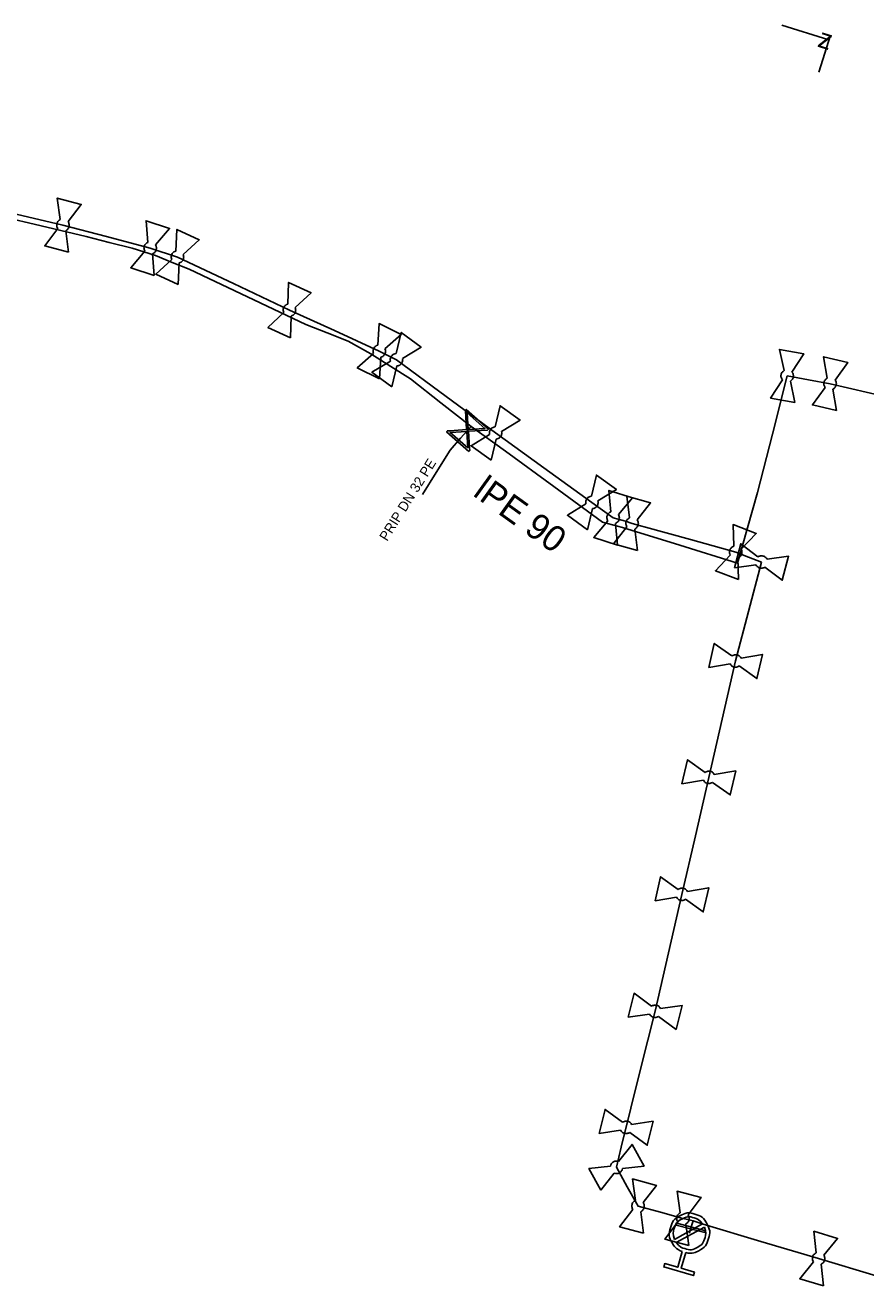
# Model space of a CAD drawing. Extents: x -638315 to -636370, y -1116147 to -1115110.
# Drawn here: x -637211.2 to -637168.7, y -1116102.1 to -1116038.4 of the extents above; entities that cross this region are included whole.
import ezdxf

# ---------------------------------------------------------------- set-up
doc = ezdxf.new("R2010")
doc.units = 0
for name, color, linetype in [('Default', 7, 'Continuous'), ('VP Hydrant', 7, 'Continuous'), ('VP Kótování', 7, 'Continuous'), ('VP Lomový bod', 7, 'Continuous'), ('VP Popis přípojky', 7, 'Continuous'), ('VP Přípojka', 7, 'Continuous'), ('VP Řad', 7, 'Continuous'), ('VP Řad - popis', 7, 'Continuous'), ('VP Šoupě', 7, 'Continuous')]:
    doc.layers.add(name, color=color, linetype=linetype)

msp = doc.modelspace()

# ---------------------------------------------------------------- linework, layer by layer
at = {"layer": 'Default'}
for points in [[(-637209.589, -1116048.648), (-637209.618, -1116048.605), (-637209.632, -1116048.553), (-637209.653, -1116048.47), (-637209.632, -1116048.391), (-637209.611, -1116048.311), (-637209.553, -1116048.251), (-637209.515, -1116048.212), (-637209.467, -1116048.189)], [(-637209.073, -1116048.293), (-637209.042, -1116048.336), (-637209.028, -1116048.389), (-637209.007, -1116048.47), (-637209.028, -1116048.549), (-637209.049, -1116048.629), (-637209.109, -1116048.691), (-637209.146, -1116048.729), (-637209.193, -1116048.752)], [(-637205.189, -1116049.793), (-637205.215, -1116049.748), (-637205.226, -1116049.696), (-637205.242, -1116049.611), (-637205.217, -1116049.533), (-637205.192, -1116049.455), (-637205.13, -1116049.399), (-637205.089, -1116049.362), (-637205.04, -1116049.342)], [(-637204.653, -1116049.468), (-637204.625, -1116049.513), (-637204.614, -1116049.567), (-637204.598, -1116049.649), (-637204.623, -1116049.727), (-637204.648, -1116049.805), (-637204.712, -1116049.863), (-637204.751, -1116049.9), (-637204.8, -1116049.92)], [(-637203.827, -1116050.207), (-637203.848, -1116050.16), (-637203.852, -1116050.106), (-637203.857, -1116050.02), (-637203.822, -1116049.946), (-637203.787, -1116049.872), (-637203.719, -1116049.824), (-637203.674, -1116049.792), (-637203.623, -1116049.779)], [(-637203.254, -1116049.953), (-637203.233, -1116050.001), (-637203.229, -1116050.056), (-637203.223, -1116050.14), (-637203.258, -1116050.214), (-637203.293, -1116050.288), (-637203.364, -1116050.338), (-637203.407, -1116050.369), (-637203.458, -1116050.382)], [(-637198.166, -1116052.891), (-637198.187, -1116052.844), (-637198.192, -1116052.79), (-637198.198, -1116052.704), (-637198.164, -1116052.63), (-637198.13, -1116052.555), (-637198.062, -1116052.506), (-637198.018, -1116052.474), (-637197.967, -1116052.46)], [(-637197.596, -1116052.63), (-637197.574, -1116052.677), (-637197.569, -1116052.732), (-637197.562, -1116052.816), (-637197.596, -1116052.89), (-637197.63, -1116052.965), (-637197.7, -1116053.016), (-637197.743, -1116053.047), (-637197.794, -1116053.061)], [(-637193.629, -1116054.963), (-637193.649, -1116054.915), (-637193.653, -1116054.861), (-637193.656, -1116054.775), (-637193.62, -1116054.702), (-637193.584, -1116054.628), (-637193.514, -1116054.581), (-637193.469, -1116054.55), (-637193.418, -1116054.537)], [(-637193.052, -1116054.718), (-637193.031, -1116054.767), (-637193.028, -1116054.821), (-637193.024, -1116054.905), (-637193.06, -1116054.978), (-637193.096, -1116055.052), (-637193.168, -1116055.101), (-637193.211, -1116055.131), (-637193.263, -1116055.144)], [(-637192.776, -1116055.34), (-637192.787, -1116055.289), (-637192.782, -1116055.236), (-637192.77, -1116055.15), (-637192.721, -1116055.084), (-637192.673, -1116055.019), (-637192.596, -1116054.984), (-637192.546, -1116054.962), (-637192.493, -1116054.958)], [(-637192.165, -1116055.201), (-637192.153, -1116055.252), (-637192.16, -1116055.306), (-637192.17, -1116055.39), (-637192.219, -1116055.456), (-637192.267, -1116055.521), (-637192.347, -1116055.557), (-637192.395, -1116055.579), (-637192.447, -1116055.583)], [(-637172.964, -1116056.288), (-637172.996, -1116056.247), (-637173.015, -1116056.197), (-637173.042, -1116056.115), (-637173.028, -1116056.035), (-637173.013, -1116055.954), (-637172.959, -1116055.889), (-637172.924, -1116055.847), (-637172.879, -1116055.821)], [(-637172.477, -1116055.893), (-637172.444, -1116055.934), (-637172.426, -1116055.985), (-637172.398, -1116056.065), (-637172.412, -1116056.145), (-637172.427, -1116056.226), (-637172.482, -1116056.293), (-637172.516, -1116056.334), (-637172.561, -1116056.36)], [(-637170.803, -1116056.666), (-637170.834, -1116056.624), (-637170.85, -1116056.572), (-637170.873, -1116056.489), (-637170.854, -1116056.41), (-637170.836, -1116056.33), (-637170.779, -1116056.268), (-637170.742, -1116056.228), (-637170.695, -1116056.203)], [(-637170.298, -1116056.295), (-637170.266, -1116056.338), (-637170.251, -1116056.39), (-637170.227, -1116056.471), (-637170.246, -1116056.55), (-637170.264, -1116056.63), (-637170.323, -1116056.694), (-637170.358, -1116056.734), (-637170.405, -1116056.758)], [(-637187.766, -1116059.043), (-637187.777, -1116058.993), (-637187.772, -1116058.939), (-637187.761, -1116058.854), (-637187.714, -1116058.787), (-637187.666, -1116058.721), (-637187.589, -1116058.686), (-637187.54, -1116058.663), (-637187.487, -1116058.659)], [(-637187.156, -1116058.897), (-637187.143, -1116058.948), (-637187.15, -1116059.003), (-637187.159, -1116059.086), (-637187.206, -1116059.153), (-637187.254, -1116059.219), (-637187.333, -1116059.255), (-637187.381, -1116059.278), (-637187.434, -1116059.282)], [(-637182.895, -1116062.553), (-637182.907, -1116062.503), (-637182.902, -1116062.45), (-637182.891, -1116062.364), (-637182.844, -1116062.297), (-637182.796, -1116062.231), (-637182.719, -1116062.196), (-637182.67, -1116062.173), (-637182.617, -1116062.169)], [(-637182.286, -1116062.407), (-637182.273, -1116062.458), (-637182.279, -1116062.512), (-637182.289, -1116062.596), (-637182.336, -1116062.663), (-637182.384, -1116062.729), (-637182.463, -1116062.765), (-637182.511, -1116062.788), (-637182.564, -1116062.792)], [(-637181.788, -1116063.414), (-637181.815, -1116063.37), (-637181.826, -1116063.317), (-637181.843, -1116063.233), (-637181.818, -1116063.155), (-637181.793, -1116063.077), (-637181.731, -1116063.02), (-637181.691, -1116062.983), (-637181.642, -1116062.962)], [(-637181.254, -1116063.087), (-637181.226, -1116063.131), (-637181.215, -1116063.185), (-637181.197, -1116063.267), (-637181.222, -1116063.345), (-637181.247, -1116063.423), (-637181.311, -1116063.482), (-637181.35, -1116063.519), (-637181.398, -1116063.539)], [(-637180.822, -1116063.714), (-637180.85, -1116063.671), (-637180.863, -1116063.619), (-637180.883, -1116063.535), (-637180.861, -1116063.456), (-637180.839, -1116063.377), (-637180.779, -1116063.318), (-637180.741, -1116063.279), (-637180.693, -1116063.257)], [(-637180.3, -1116063.367), (-637180.27, -1116063.41), (-637180.257, -1116063.464), (-637180.237, -1116063.545), (-637180.259, -1116063.624), (-637180.281, -1116063.703), (-637180.342, -1116063.764), (-637180.38, -1116063.802), (-637180.428, -1116063.824)], [(-637175.597, -1116065.139), (-637175.621, -1116065.093), (-637175.629, -1116065.04), (-637175.641, -1116064.954), (-637175.612, -1116064.878), (-637175.582, -1116064.801), (-637175.517, -1116064.748), (-637175.475, -1116064.713), (-637175.425, -1116064.696)], [(-637175.045, -1116064.842), (-637175.019, -1116064.889), (-637175.011, -1116064.943), (-637174.999, -1116065.026), (-637175.028, -1116065.102), (-637175.058, -1116065.179), (-637175.125, -1116065.234), (-637175.165, -1116065.268), (-637175.215, -1116065.285)], [(-637173.843, -1116065.747), (-637173.886, -1116065.778), (-637173.939, -1116065.791), (-637174.02, -1116065.813), (-637174.099, -1116065.792), (-637174.178, -1116065.772), (-637174.241, -1116065.711), (-637174.279, -1116065.675), (-637174.302, -1116065.627)], [(-637174.198, -1116065.231), (-637174.155, -1116065.202), (-637174.104, -1116065.188), (-637174.02, -1116065.167), (-637173.941, -1116065.188), (-637173.862, -1116065.208), (-637173.801, -1116065.267), (-637173.762, -1116065.305), (-637173.739, -1116065.353)], [(-637175.516, -1116070.237), (-637175.474, -1116070.206), (-637175.423, -1116070.191), (-637175.34, -1116070.167), (-637175.26, -1116070.185), (-637175.18, -1116070.204), (-637175.118, -1116070.261), (-637175.078, -1116070.297), (-637175.054, -1116070.344)], [(-637175.145, -1116070.742), (-637175.187, -1116070.773), (-637175.24, -1116070.789), (-637175.32, -1116070.813), (-637175.4, -1116070.795), (-637175.48, -1116070.776), (-637175.544, -1116070.718), (-637175.583, -1116070.682), (-637175.608, -1116070.635)], [(-637176.495, -1116076.622), (-637176.537, -1116076.653), (-637176.59, -1116076.669), (-637176.67, -1116076.693), (-637176.75, -1116076.675), (-637176.83, -1116076.656), (-637176.894, -1116076.598), (-637176.933, -1116076.562), (-637176.958, -1116076.515)], [(-637176.866, -1116076.117), (-637176.824, -1116076.086), (-637176.773, -1116076.071), (-637176.69, -1116076.047), (-637176.61, -1116076.065), (-637176.53, -1116076.084), (-637176.468, -1116076.141), (-637176.428, -1116076.178), (-637176.403, -1116076.224)], [(-637178.226, -1116082.027), (-637178.184, -1116081.996), (-637178.133, -1116081.981), (-637178.05, -1116081.957), (-637177.97, -1116081.975), (-637177.89, -1116081.994), (-637177.828, -1116082.051), (-637177.788, -1116082.088), (-637177.763, -1116082.134)], [(-637177.855, -1116082.532), (-637177.897, -1116082.563), (-637177.95, -1116082.579), (-637178.03, -1116082.603), (-637178.11, -1116082.585), (-637178.19, -1116082.566), (-637178.254, -1116082.508), (-637178.293, -1116082.472), (-637178.318, -1116082.425)], [(-637179.581, -1116087.933), (-637179.538, -1116087.904), (-637179.487, -1116087.889), (-637179.403, -1116087.867), (-637179.324, -1116087.887), (-637179.245, -1116087.907), (-637179.184, -1116087.965), (-637179.144, -1116088.003), (-637179.121, -1116088.05)], [(-637179.22, -1116088.445), (-637179.263, -1116088.476), (-637179.316, -1116088.491), (-637179.397, -1116088.513), (-637179.476, -1116088.493), (-637179.555, -1116088.473), (-637179.618, -1116088.413), (-637179.657, -1116088.377), (-637179.68, -1116088.33)], [(-637181.042, -1116093.796), (-637181, -1116093.766), (-637180.948, -1116093.751), (-637180.865, -1116093.729), (-637180.786, -1116093.749), (-637180.706, -1116093.769), (-637180.645, -1116093.826), (-637180.605, -1116093.864), (-637180.582, -1116093.911)], [(-637180.68, -1116094.307), (-637180.723, -1116094.338), (-637180.775, -1116094.353), (-637180.856, -1116094.375), (-637180.936, -1116094.356), (-637181.015, -1116094.336), (-637181.078, -1116094.276), (-637181.117, -1116094.24), (-637181.141, -1116094.193)], [(-637181.658, -1116096.006), (-637181.647, -1116095.956), (-637181.619, -1116095.91), (-637181.573, -1116095.837), (-637181.502, -1116095.797), (-637181.43, -1116095.757), (-637181.346, -1116095.758), (-637181.292, -1116095.758), (-637181.242, -1116095.777)], [(-637181.044, -1116096.133), (-637181.054, -1116096.185), (-637181.083, -1116096.231), (-637181.127, -1116096.303), (-637181.198, -1116096.343), (-637181.27, -1116096.383), (-637181.357, -1116096.382), (-637181.41, -1116096.382), (-637181.459, -1116096.364)], [(-637180.521, -1116098.206), (-637180.549, -1116098.162), (-637180.563, -1116098.111), (-637180.583, -1116098.027), (-637180.561, -1116097.948), (-637180.54, -1116097.869), (-637180.481, -1116097.809), (-637180.442, -1116097.77), (-637180.394, -1116097.748)], [(-637180.001, -1116097.855), (-637179.971, -1116097.899), (-637179.958, -1116097.952), (-637179.937, -1116098.033), (-637179.959, -1116098.112), (-637179.98, -1116098.191), (-637180.041, -1116098.253), (-637180.078, -1116098.291), (-637180.126, -1116098.313)], [(-637178.023, -1116100.332), (-637178.36, -1116100.205), (-637178.536, -1116099.884), (-637178.735, -1116099.522), (-637178.621, -1116099.122), (-637178.507, -1116098.724), (-637178.144, -1116098.525), (-637177.782, -1116098.325), (-637177.382, -1116098.439), (-637176.986, -1116098.553), (-637176.785, -1116098.914), (-637176.584, -1116099.276), (-637176.698, -1116099.674), (-637176.813, -1116100.074), (-637177.173, -1116100.275), (-637177.493, -1116100.456), (-637177.846, -1116100.383)], [(-637176.996, -1116098.928), (-637177.157, -1116098.701), (-637177.435, -1116098.621), (-637177.758, -1116098.529), (-637178.052, -1116098.691), (-637178.347, -1116098.854), (-637178.44, -1116099.178), (-637178.519, -1116099.456), (-637178.412, -1116099.713)], [(-637178.248, -1116098.83), (-637178.277, -1116098.787), (-637178.291, -1116098.736), (-637178.313, -1116098.652), (-637178.293, -1116098.573), (-637178.273, -1116098.494), (-637178.214, -1116098.433), (-637178.177, -1116098.393), (-637178.129, -1116098.37)], [(-637177.734, -1116098.471), (-637177.703, -1116098.514), (-637177.689, -1116098.567), (-637177.667, -1116098.648), (-637177.687, -1116098.727), (-637177.707, -1116098.806), (-637177.767, -1116098.869), (-637177.804, -1116098.908), (-637177.851, -1116098.931)], [(-637178.324, -1116099.872), (-637178.164, -1116100.103), (-637177.883, -1116100.183), (-637177.558, -1116100.277), (-637177.264, -1116100.114), (-637176.971, -1116099.951), (-637176.878, -1116099.626), (-637176.797, -1116099.345), (-637176.908, -1116099.087)], [(-637171.395, -1116100.849), (-637171.422, -1116100.805), (-637171.435, -1116100.753), (-637171.453, -1116100.669), (-637171.429, -1116100.59), (-637171.406, -1116100.512), (-637171.345, -1116100.454), (-637171.306, -1116100.416), (-637171.257, -1116100.395)], [(-637170.867, -1116100.511), (-637170.838, -1116100.556), (-637170.826, -1116100.609), (-637170.807, -1116100.691), (-637170.831, -1116100.77), (-637170.854, -1116100.848), (-637170.917, -1116100.908), (-637170.954, -1116100.945), (-637171.003, -1116100.966)]]:
    msp.add_open_spline(points, degree=3, dxfattribs=at)
at = {"layer": 'VP Hydrant'}
for points in [[(-637178.412, -1116099.713), (-637176.996, -1116098.928)], [(-637176.908, -1116099.087), (-637178.324, -1116099.872)], [(-637177.846, -1116100.383), (-637178.072, -1116101.171), (-637177.41, -1116101.361), (-637177.46, -1116101.538), (-637178.962, -1116101.107), (-637178.912, -1116100.931), (-637178.249, -1116101.121), (-637178.023, -1116100.332)]]:
    msp.add_lwpolyline(points, dxfattribs=at)
at = {"layer": 'VP Kótování'}
for points in [[(-637172.998, -1116038.369), (-637170.611, -1116039.112)], [(-637171.117, -1116040.739), (-637170.536, -1116038.874)]]:
    msp.add_lwpolyline(points, dxfattribs=at)
at = {"layer": 'VP Lomový bod'}
for points in [[(-637209.467, -1116048.189), (-637209.616, -1116047.102), (-637208.408, -1116047.42), (-637209.073, -1116048.293)], [(-637205.04, -1116049.342), (-637205.127, -1116048.248), (-637203.938, -1116048.635), (-637204.653, -1116049.468)], [(-637209.044, -1116049.838), (-637210.252, -1116049.52), (-637209.589, -1116048.648)], [(-637209.193, -1116048.752), (-637209.044, -1116049.838)], [(-637203.623, -1116049.779), (-637203.57, -1116048.683), (-637202.44, -1116049.218), (-637203.254, -1116049.953)], [(-637204.713, -1116051.012), (-637205.902, -1116050.625), (-637205.189, -1116049.793)], [(-637204.8, -1116049.92), (-637204.713, -1116051.012)], [(-637203.51, -1116051.477), (-637204.64, -1116050.942), (-637203.827, -1116050.207)], [(-637203.458, -1116050.382), (-637203.51, -1116051.477)], [(-637197.967, -1116052.46), (-637197.928, -1116051.363), (-637196.791, -1116051.884), (-637197.596, -1116052.63)], [(-637197.832, -1116054.157), (-637198.969, -1116053.636), (-637198.166, -1116052.891)], [(-637197.794, -1116053.061), (-637197.832, -1116054.157)], [(-637193.418, -1116054.537), (-637193.346, -1116053.442), (-637192.226, -1116053.996), (-637193.052, -1116054.718)], [(-637192.493, -1116054.958), (-637192.23, -1116053.893), (-637191.225, -1116054.636), (-637192.165, -1116055.201)], [(-637172.879, -1116055.821), (-637173.114, -1116054.749), (-637171.884, -1116054.97), (-637172.477, -1116055.893)], [(-637193.334, -1116056.238), (-637194.454, -1116055.684), (-637193.629, -1116054.963)], [(-637192.71, -1116056.647), (-637193.715, -1116055.904), (-637192.776, -1116055.34)], [(-637193.263, -1116055.144), (-637193.334, -1116056.238)], [(-637192.447, -1116055.583), (-637192.71, -1116056.647)], [(-637170.695, -1116056.203), (-637170.877, -1116055.121), (-637169.659, -1116055.403), (-637170.298, -1116056.295)], [(-637172.326, -1116057.431), (-637173.556, -1116057.21), (-637172.964, -1116056.288)], [(-637172.561, -1116056.36), (-637172.326, -1116057.431)], [(-637170.223, -1116057.839), (-637171.441, -1116057.557), (-637170.803, -1116056.666)], [(-637170.405, -1116056.758), (-637170.223, -1116057.839)], [(-637187.487, -1116058.659), (-637187.236, -1116057.591), (-637186.222, -1116058.321), (-637187.156, -1116058.897)], [(-637187.684, -1116060.349), (-637188.698, -1116059.619), (-637187.766, -1116059.043)], [(-637187.434, -1116059.282), (-637187.684, -1116060.349)], [(-637182.617, -1116062.169), (-637182.367, -1116061.1), (-637181.353, -1116061.83), (-637182.286, -1116062.407)], [(-637181.642, -1116062.962), (-637181.734, -1116061.869), (-637180.544, -1116062.25), (-637181.254, -1116063.087)], [(-637182.813, -1116063.86), (-637183.827, -1116063.13), (-637182.895, -1116062.553)], [(-637180.693, -1116063.257), (-637180.826, -1116062.168), (-637179.622, -1116062.504), (-637180.3, -1116063.367)], [(-637182.564, -1116062.792), (-637182.813, -1116063.86)], [(-637181.306, -1116064.631), (-637182.496, -1116064.25), (-637181.788, -1116063.414)], [(-637180.294, -1116064.912), (-637181.498, -1116064.576), (-637180.822, -1116063.714)], [(-637181.398, -1116063.539), (-637181.306, -1116064.631)], [(-637180.428, -1116063.824), (-637180.294, -1116064.912)], [(-637175.425, -1116064.696), (-637175.455, -1116063.599), (-637174.288, -1116064.048), (-637175.045, -1116064.842)], [(-637175.185, -1116066.381), (-637176.352, -1116065.932), (-637175.597, -1116065.139)], [(-637175.388, -1116065.778), (-637175.071, -1116064.569), (-637174.198, -1116065.231)], [(-637174.302, -1116065.627), (-637175.388, -1116065.778)], [(-637175.215, -1116065.285), (-637175.185, -1116066.381)], [(-637173.739, -1116065.353), (-637172.652, -1116065.202), (-637172.969, -1116066.411), (-637173.843, -1116065.747)], [(-637176.688, -1116070.819), (-637176.408, -1116069.601), (-637175.516, -1116070.237)], [(-637175.054, -1116070.344), (-637173.972, -1116070.161), (-637174.252, -1116071.379), (-637175.145, -1116070.742)], [(-637175.608, -1116070.635), (-637176.688, -1116070.819)], [(-637178.038, -1116076.699), (-637177.758, -1116075.481), (-637176.866, -1116076.117)], [(-637176.958, -1116076.515), (-637178.038, -1116076.699)], [(-637176.403, -1116076.224), (-637175.322, -1116076.041), (-637175.602, -1116077.259), (-637176.495, -1116076.622)], [(-637179.398, -1116082.609), (-637179.118, -1116081.391), (-637178.226, -1116082.027)], [(-637177.763, -1116082.134), (-637176.682, -1116081.951), (-637176.962, -1116083.169), (-637177.855, -1116082.532)], [(-637178.318, -1116082.425), (-637179.398, -1116082.609)], [(-637180.765, -1116088.492), (-637180.46, -1116087.28), (-637179.581, -1116087.933)], [(-637179.121, -1116088.05), (-637178.035, -1116087.888), (-637178.34, -1116089.1), (-637179.22, -1116088.445)], [(-637179.68, -1116088.33), (-637180.765, -1116088.492)], [(-637182.224, -1116094.359), (-637181.924, -1116093.145), (-637181.042, -1116093.796)], [(-637180.582, -1116093.911), (-637179.497, -1116093.746), (-637179.797, -1116094.959), (-637180.68, -1116094.307)], [(-637181.141, -1116094.193), (-637182.224, -1116094.359)], [(-637181.242, -1116095.777), (-637180.561, -1116094.916), (-637179.954, -1116096.009), (-637181.044, -1116096.133)], [(-637182.139, -1116097.224), (-637182.746, -1116096.131), (-637181.658, -1116096.006)], [(-637181.459, -1116096.364), (-637182.139, -1116097.224)], [(-637180.394, -1116097.748), (-637180.534, -1116096.659), (-637179.328, -1116096.989), (-637180.001, -1116097.855)], [(-637178.129, -1116098.37), (-637178.287, -1116097.284), (-637177.076, -1116097.593), (-637177.734, -1116098.471)], [(-637179.986, -1116099.401), (-637181.192, -1116099.071), (-637180.521, -1116098.206)], [(-637180.126, -1116098.313), (-637179.986, -1116099.401)], [(-637177.693, -1116100.016), (-637178.904, -1116099.707), (-637178.248, -1116098.83)], [(-637177.851, -1116098.931), (-637177.693, -1116100.016)], [(-637171.257, -1116100.395), (-637171.371, -1116099.303), (-637170.173, -1116099.661), (-637170.867, -1116100.511)], [(-637170.889, -1116102.057), (-637172.087, -1116101.699), (-637171.395, -1116100.849)], [(-637171.003, -1116100.966), (-637170.889, -1116102.057)]]:
    msp.add_lwpolyline(points, dxfattribs=at)
at = {"layer": 'VP Přípojka'}
for points in [[(-637188.7, -1116058.64), (-637188.879, -1116058.842), (-637189.23, -1116059.24), (-637189.76, -1116059.84), (-637190.46, -1116060.96), (-637191.16, -1116062.08)], [(-637177.66, -1116099.4), (-637177.59, -1116099.13), (-637177.48, -1116098.78)]]:
    msp.add_lwpolyline(points, dxfattribs=at)
at = {"layer": 'VP Řad'}
for points in [[(-637167.635, -1116057.155), (-637170.55, -1116056.48), (-637171.635, -1116056.285), (-637172.72, -1116056.09), (-637173.47, -1116059.035), (-637174.22, -1116061.98), (-637174.73, -1116063.76), (-637175.24, -1116065.54), (-637178.14, -1116064.64), (-637181.04, -1116063.74), (-637181.55, -1116063.605), (-637182.06, -1116063.47), (-637184.51, -1116061.68), (-637186.96, -1116059.89), (-637188.7, -1116058.64), (-637190.23, -1116057.44), (-637191.76, -1116056.24), (-637192.76, -1116055.605), (-637193.76, -1116054.97), (-637194.335, -1116054.65), (-637194.91, -1116054.33), (-637195.98, -1116053.91), (-637197.05, -1116053.49), (-637200, -1116052.09), (-637202.95, -1116050.69), (-637203.805, -1116050.35), (-637204.66, -1116050.01), (-637205.245, -1116049.825), (-637205.83, -1116049.64), (-637206.995, -1116049.34), (-637208.16, -1116049.04), (-637211.07, -1116048.36), (-637213.98, -1116047.68)], [(-637168.22, -1116101.55), (-637171.13, -1116100.68), (-637174.05, -1116099.815), (-637176.97, -1116098.95), (-637177.225, -1116098.865), (-637177.48, -1116098.78), (-637177.735, -1116098.715), (-637177.99, -1116098.65), (-637179.125, -1116098.34), (-637180.26, -1116098.03), (-637180.805, -1116097.05), (-637181.35, -1116096.07), (-637181.11, -1116095.06), (-637180.135, -1116091.12), (-637179.4, -1116088.19), (-637178.72, -1116085.235), (-637178.04, -1116082.28), (-637177.36, -1116079.325), (-637176.68, -1116076.37), (-637176.005, -1116073.43), (-637175.33, -1116070.49), (-637174.675, -1116067.99), (-637174.02, -1116065.49), (-637174.67, -1116065.24), (-637175.32, -1116064.99), (-637177.6, -1116064.36), (-637179.88, -1116063.73), (-637180.13, -1116063.66), (-637180.56, -1116063.54), (-637180.9, -1116063.42), (-637181.27, -1116063.33), (-637181.52, -1116063.25), (-637182.055, -1116062.865), (-637182.59, -1116062.48), (-637185.025, -1116060.725), (-637187.46, -1116058.97), (-637189.965, -1116057.12), (-637192.47, -1116055.27), (-637193.34, -1116054.84), (-637195.61, -1116053.8), (-637197.88, -1116052.76), (-637200.71, -1116051.42), (-637203.54, -1116050.08), (-637204.92, -1116049.63), (-637207.125, -1116049.05), (-637209.33, -1116048.47), (-637212.265, -1116047.785)]]:
    msp.add_lwpolyline(points, dxfattribs=at)
at = {"layer": 'VP Šoupě'}
for points in [[(-637188.814, -1116059.902), (-637189.938, -1116058.909), (-637189.895, -1116058.86), (-637189.766, -1116058.856), (-637188.928, -1116058.803), (-637188.989, -1116057.834), (-637188.945, -1116057.785), (-637187.821, -1116058.778), (-637187.865, -1116058.827), (-637188.835, -1116058.885), (-637188.782, -1116059.724), (-637188.77, -1116059.853), (-637188.814, -1116059.902)], [(-637188.813, -1116059.901), (-637189.937, -1116058.908), (-637189.894, -1116058.858), (-637189.765, -1116058.855), (-637188.927, -1116058.802), (-637188.988, -1116057.833), (-637188.944, -1116057.784), (-637187.82, -1116058.777), (-637187.864, -1116058.826), (-637188.833, -1116058.884), (-637188.78, -1116059.722), (-637188.769, -1116059.851), (-637188.813, -1116059.901)], [(-637188.893, -1116057.956), (-637188.84, -1116058.797), (-637188.001, -1116058.744), (-637188.893, -1116057.956)], [(-637188.892, -1116057.955), (-637188.839, -1116058.796), (-637187.999, -1116058.743), (-637188.892, -1116057.955)], [(-637188.87, -1116059.728), (-637188.922, -1116058.891), (-637189.758, -1116058.943), (-637188.87, -1116059.728)], [(-637188.869, -1116059.726), (-637188.921, -1116058.889), (-637189.757, -1116058.942), (-637188.869, -1116059.726)], [(-637178.304, -1116098.896), (-637176.852, -1116099.273), (-637176.876, -1116099.364), (-637178.328, -1116098.987), (-637178.304, -1116098.896)]]:
    msp.add_lwpolyline(points, dxfattribs=at)

# ---------------------------------------------------------------- texts
at = {"layer": 'VP Kótování'}
msp.add_text('z', height=1, rotation=342.71423, dxfattribs=at).set_placement((-637171.237, -1116039.441))
at = {"layer": 'VP Popis přípojky'}
msp.add_text('PRIP DN 32 PE', height=0.5, rotation=57.99462, dxfattribs=at).set_placement((-637192.944, -1116064.476))
at = {"layer": 'VP Řad - popis'}
msp.add_text('lPE 90', height=1.3, rotation=324.30688, dxfattribs=at).set_placement((-637188.659, -1116062.106))

doc.saveas('drawing.dxf')
